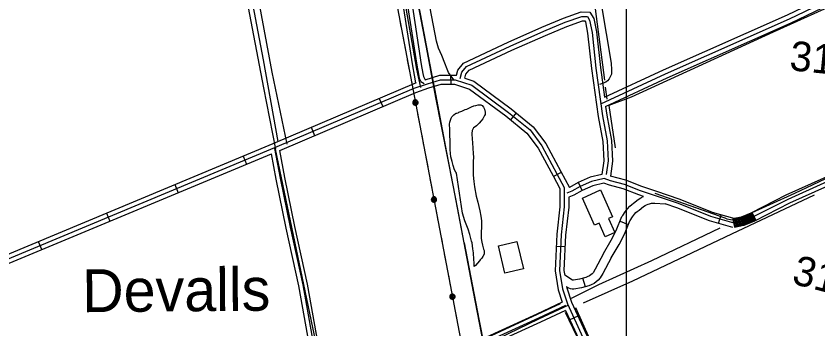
# Model space of a CAD drawing. Extents: x 3281947 to 3319794, y 715894 to 741249.
# Drawn here: x 3289265 to 3291976, y 736024 to 737081 of the extents above; entities that cross this region are included whole.
import ezdxf

# ---------------------------------------------------------------- set-up
doc = ezdxf.new("R2010")
doc.units = 0
for name, color, linetype in [('V-BLDG-OTLN', 7, 'Continuous'), ('V-DTCH-CNTR', 7, 'Continuous'), ('V-GRID-MAJR', 7, 'Continuous'), ('V-RAIL-TRAK', 7, 'Continuous'), ('V-ROAD-CNTR', 7, 'Continuous'), ('V-SITE-VEGE', 7, 'Continuous'), ('V-SURV-IDEN', 7, 'Continuous'), ('V-TOPO-GNAM-IDEN', 7, 'Continuous'), ('V-TOPO-SHOR', 7, 'Continuous'), ('V-UTIL-LINE', 7, 'Continuous')]:
    doc.layers.add(name, color=color, linetype=linetype)

msp = doc.modelspace()

# ---------------------------------------------------------------- linework, layer by layer
at = {"layer": 'V-BLDG-OTLN'}
for points in [[(3291281.8, 736402.7), (3291268.2, 736396.7), (3291289.1, 736349.7), (3291256.8, 736335.3), (3291236.1, 736381.7), (3291220.9, 736374.8), (3291180.2, 736466.2), (3291241.4, 736493.5)], [(3290958.2, 736319.6), (3290980.2, 736226.6), (3290917.7, 736211.8), (3290895.7, 736304.8)]]:
    msp.add_lwpolyline(points, close=True, dxfattribs=at)
at = {"layer": 'V-DTCH-CNTR'}
for points in [[(3290745.6, 736866.2), (3290727.6, 736890.9), (3290722.3, 736902.1), (3290714.4, 736922.2), (3290704.5, 736948), (3290693.2, 736973.1), (3290686.4, 736995.8), (3290608.7, 737401.9), (3290536.4, 737765.5), (3290428.6, 738333.3), (3290393, 738535.1), (3290545, 738549.1), (3290994.2, 738579.2), (3291010.3, 738578), (3291022.3, 738581), (3291034.6, 738586.7), (3291052.8, 738599.3), (3291065.5, 738604.9), (3291154.1, 738614), (3291554.3, 738636.3), (3291943.1, 738660), (3292376.8, 738680.9), (3292786.6, 738694), (3292937.7, 738730.9)], [(3291032.4, 738585.6), (3291072.4, 738319.9), (3291138.8, 737827.8), (3291242.7, 737123.1), (3291276.4, 736921.6), (3291278.1, 736899.7), (3291278.4, 736885.1), (3291270.6, 736869), (3291264.8, 736862.1), (3291259, 736857.5), (3291244.4, 736851.8), (3291238, 736849.9)], [(3290181.6, 736648), (3290131, 736891.1), (3290043.8, 737358.9), (3290013.9, 737491.6), (3289988.3, 737645.4), (3289930, 737941.6), (3289885.4, 738191.9), (3289823.9, 738505.8)], [(3289978.8, 737485.8), (3290020.7, 737264), (3290102.2, 736839), (3290142.3, 736631.8)], [(3290633.2, 736839.4), (3290619.8, 736901.3), (3290552.9, 737288.9)], [(3290314.7, 735730.3), (3290307.7, 735763), (3290298.4, 735883.4), (3290142.4, 736631.8)], [(3291133.2, 736103.4), (3291031.4, 736056.1), (3290894, 735990.4), (3290846.5, 735970.1)]]:
    msp.add_lwpolyline(points, dxfattribs=at)
at = {"layer": 'V-GRID-MAJR'}
msp.add_spline([(3291333.3, 721274), (3291331.5, 727333.8), (3291329.7, 733395.6), (3291328, 739457.3), (3291328, 739459.2)], degree=3, dxfattribs=at)
at = {"layer": 'V-RAIL-TRAK'}
for points in [[(3290780.3, 736314.3), (3290757.2, 736433.9), (3290722, 736620), (3290680.9, 736835.5), (3290673.1, 736874.7), (3290632.7, 737089.1), (3290589.9, 737311.7), (3290545.4, 737544.7), (3290504.4, 737757.4), (3290479.9, 737886.3), (3290444.8, 738070.3), (3290404.9, 738279.3), (3290360.8, 738509.8), (3290343.6, 738600.9), (3290298.1, 738836.8), (3290271.7, 738975.7), (3290237.6, 739154), (3290209.7, 739299.3), (3290186.4, 739422.1), (3290179.4, 739458.6)], [(3290780.3, 736314.3), (3290830.7, 736051.5), (3290846.4, 735970.5), (3290889.8, 735740.8), (3290942.3, 735469.4), (3291020.2, 735058.8), (3291065.3, 734823.3), (3291076.5, 734767.4), (3291091.3, 734689.9), (3291149.4, 734384.3), (3291181.5, 734219.5), (3291239.8, 733915.7), (3291314, 733529.1)]]:
    msp.add_lwpolyline(points, dxfattribs=at)
at = {"layer": 'V-ROAD-CNTR'}
for p, q in [((3290734.4, 736881.1), (3290734.5, 736851.1)), ((3290492.8, 736803.1), (3290504.6, 736775.5)), ((3290955.5, 736753.8), (3290936.6, 736730.5)), ((3290262.9, 736705.1), (3290274.6, 736677.5)), ((3290032.6, 736607.9), (3290044.2, 736580.2)), ((3291108.4, 736552.7), (3291081.9, 736538.7)), ((3289801.9, 736511.6), (3289813.5, 736483.9)), ((3291178.4, 736491.5), (3291166.4, 736519)), ((3289571.2, 736415.3), (3289582.8, 736387.6)), ((3291640, 736380.3), (3291648.2, 736409.2)), ((3291766.8, 736390.6), (3291753.3, 736417.3)), ((3291307, 736387.7), (3291334.8, 736376.4)), ((3289340.5, 736319), (3289352.1, 736291.3)), ((3291120.9, 736301.5), (3291090.9, 736302.8)), ((3291189.8, 736166), (3291181.6, 736194.8)), ((3291164.5, 736066.7), (3291137.2, 736054.2))]:
    msp.add_line(p, q, dxfattribs=at)
for points in [[(3290886.8, 735758.9), (3290812, 736149.3), (3290743.6, 736503.8), (3290684.6, 736806.4), (3290656.4, 736958.5), (3290548.8, 737517.9), (3290453.2, 738000.2), (3290363.1, 738472.4), (3290315, 738745.8), (3290226.2, 739200.2), (3290176.4, 739461.4)], [(3290268.9, 738539.2), (3290285.3, 738532.7), (3290304.8, 738512.6), (3290319.6, 738485), (3290337.2, 738443), (3290364.8, 738252.8), (3290377.4, 738195.5), (3290432.7, 737922.3), (3290500.7, 737628.6), (3290547.2, 737393.3), (3290603.8, 737119.1), (3290634.8, 736918), (3290640, 736887.3), (3290642.2, 736876.6), (3290648.1, 736865.6)], [(3290257.8, 738511.4), (3290268.2, 738507.2), (3290280.3, 738494.7), (3290292.5, 738472), (3290308.1, 738434.9), (3290335.3, 738247.5), (3290348, 738189.3), (3290403.4, 737915.9), (3290471.4, 737622.3), (3290517.8, 737387.3), (3290574.3, 737113.8), (3290605.2, 736913.2), (3290610.5, 736881.8), (3290615.9, 736855.5)], [(3290263.4, 738525.3), (3290276.8, 738519.9), (3290292.6, 738503.6), (3290306.1, 738478.5), (3290322.7, 738438.9), (3290350, 738250.2), (3290362.7, 738192.4), (3290418, 737919.1), (3290486, 737625.5), (3290532.5, 737390.3), (3290589, 737116.5), (3290620, 736915.6), (3290625.3, 736884.6), (3290628, 736871.4), (3290633.9, 736860.3), (3290644.5, 736853.7)], [(3291241.4, 736787.2), (3291241.7, 736784.6), (3291460.3, 736885.8), (3291879.5, 737072.1), (3292223, 737237.4), (3292795.7, 737492.3), (3292914.8, 737541.1), (3292968, 737567.7), (3293028.6, 737610.2), (3293062.5, 737666.1), (3293080.1, 737727.3), (3293105.3, 737794.5), (3293119.6, 737822.1), (3293150.7, 737838.2), (3293189.3, 737842.9), (3293244.7, 737860.5), (3293372, 737886.6), (3293435.9, 737899.1), (3293463.4, 737912.1), (3293491.3, 737922.1), (3293510.8, 737922.1)], [(3291258.1, 736775.6), (3291466.5, 736872.1), (3291885.8, 737058.5), (3292229.3, 737223.7), (3292801.6, 737478.5), (3292921.1, 737527.5), (3292975.7, 737554.8), (3293039.8, 737599.8), (3293076.4, 737660.1), (3293094.4, 737722.6), (3293119, 737788.4), (3293130.8, 737811), (3293155.2, 737823.7), (3293192.5, 737828.2), (3293248.5, 737845.9), (3293374.9, 737871.9), (3293440.6, 737884.7), (3293469.1, 737898.2), (3293493.9, 737907.1), (3293506.2, 737907.1)], [(3291253.9, 736806.8), (3291454.1, 736899.4), (3291873.2, 737085.7), (3292216.7, 737251), (3292427.8, 737344.9)], [(3290753.7, 736881.2), (3290758.9, 736898.8), (3290778.3, 736922.5), (3290929.1, 736992.8), (3291042.9, 737043.5), (3291116.2, 737074.1), (3291175.6, 737095), (3291205.2, 737094.3), (3291218.2, 737072.9), (3291227, 737027.9), (3291240.5, 736907.1), (3291253.9, 736806.8)], [(3290766.1, 736870.4), (3290772.4, 736891.6), (3290787.8, 736910.3), (3290935.3, 736979.2), (3291048.8, 737029.7), (3291121.5, 737060.1), (3291178, 737080), (3291196.7, 737079.5), (3291204, 737067.4), (3291212.2, 737025.6), (3291225.6, 736905.2), (3291247.2, 736744), (3291263.4, 736659), (3291266.8, 736591.3), (3291260.1, 736545.7)], [(3290782, 736871.4), (3290786, 736884.4), (3290797.2, 736898.2), (3290941.5, 736965.5), (3291054.8, 737016), (3291126.9, 737046.1), (3291180.4, 737064.9), (3291188.1, 737064.7), (3291189.8, 737061.9), (3291197.4, 737023.4), (3291210.7, 736903.4), (3291232.4, 736741.6), (3291248.5, 736657.2), (3291251.7, 736592.1), (3291244.9, 736545.4)], [(3292925.4, 736982.2), (3292913.3, 736977.5), (3292820.1, 736927.3), (3292579.1, 736805.6), (3292123.6, 736590.9), (3291867.3, 736475.3), (3291748.8, 736415), (3291716, 736401.8), (3291686.7, 736395.3)], [(3292930.8, 736968.2), (3292919.7, 736963.9), (3292827, 736914), (3292585.7, 736792.1), (3292129.9, 736577.3), (3291873.8, 736461.7), (3291755, 736401.4), (3291720.4, 736387.4), (3291689.9, 736380.7)], [(3292936.3, 736954.2), (3292926, 736950.2), (3292834, 736900.7), (3292592.3, 736778.6), (3292136.1, 736563.7), (3291880.2, 736448.2), (3291761.2, 736387.7), (3291724.9, 736373.1), (3291693.2, 736366)], [(3290648.1, 736865.6), (3290698.1, 736881), (3290753.7, 736881.2)], [(3286857.3, 734823), (3286878.9, 734837.3), (3287235, 735145.3), (3287700.1, 735562.8), (3287789.7, 735640.6), (3287842.8, 735673), (3288015.8, 735751.1), (3288317.9, 735887.9), (3289230.7, 736273.2), (3290134.7, 736650.5), (3290618.8, 736856.8)], [(3289236.5, 736259.3), (3290140.5, 736636.7), (3290610.8, 736837.1), (3290656, 736852.3), (3290700.4, 736866), (3290749.6, 736866.2), (3290805.5, 736848.1), (3290929.9, 736755.2), (3291002.9, 736696.1), (3291043, 736642.7), (3291093.7, 736548.4), (3291118.3, 736502.1), (3291118.3, 736435.9), (3291107.6, 736342.2), (3291102.3, 736220.8), (3291112.3, 736159.3), (3291128.8, 736108.6), (3291180.7, 735995.2), (3291318.5, 735695.6), (3291379, 735564.7), (3291428.4, 735472.4), (3291519, 735320.2), (3291679.9, 735056.4)], [(3290782, 736871.4), (3290812.5, 736861.6), (3290939.1, 736767.1), (3291013.7, 736706.6), (3291055.7, 736650.8), (3291106.9, 736555.5), (3291135.5, 736501.8)], [(3290156.8, 736627.3), (3290616.2, 736823), (3290660.6, 736838.1), (3290702.7, 736851), (3290747.3, 736851.2), (3290798.5, 736834.6), (3290920.7, 736743.4), (3290992, 736685.6), (3291030.3, 736634.6), (3291080.4, 736541.4), (3291103.3, 736498.4), (3291103.3, 736436.7), (3291092.7, 736343.4), (3291087.2, 736219.9), (3291097.7, 736155.8), (3291111.3, 736113.9)], [(3291258.1, 736775.6), (3291262, 736746.4), (3291278.3, 736660.8), (3291281.9, 736590.6), (3291274.5, 736540.2)], [(3288252, 735825.2), (3288330, 735860.4), (3289242.3, 736245.5), (3290128.5, 736615.4)], [(3290293.7, 735737.2), (3290283.4, 735827.6), (3290251.4, 735999.1), (3290221.4, 736169.3), (3290178.5, 736364.1), (3290144.5, 736530), (3290128.5, 736615.4)], [(3290314.4, 735733.1), (3290309.8, 735728.2), (3290298.3, 735829.8), (3290266.2, 736001.8), (3290236.2, 736172.2), (3290193.2, 736367.2), (3290159.2, 736532.9), (3290140.4, 736633.7)], [(3290322.4, 735750.5), (3290313.1, 735832), (3290281, 736004.4), (3290250.9, 736175.1), (3290207.8, 736370.3), (3290174, 736535.8), (3290156.8, 736627.3)], [(3291692.2, 736381.2), (3291614.1, 736403.3), (3291504.5, 736447.4), (3291423.6, 736475.1), (3291375.6, 736491), (3291322.1, 736511.9), (3291275, 736524.5), (3291252.9, 736531.9), (3291210.2, 736521.8), (3291172.4, 736505.2), (3291144.1, 736489.4), (3291126.6, 736482.4)], [(3291244.9, 736545.4), (3291205.4, 736536.1), (3291165.7, 736518.7), (3291135.5, 736501.8)], [(3291696.3, 736395.6), (3291619, 736417.5), (3291509.8, 736461.4), (3291428.4, 736489.3), (3291380.7, 736505.2), (3291326.8, 736526.2), (3291274.5, 736540.2)], [(3291386.7, 736471.6), (3291370.6, 736476.9), (3291317.4, 736497.6), (3291270.7, 736510.1), (3291252.2, 736516.3), (3291215, 736507.5), (3291179.1, 736491.8), (3291150.6, 736475.9), (3291133.3, 736468.9)], [(3291133.3, 736468.9), (3291133.3, 736435), (3291122.6, 736341.1), (3291117.3, 736221.7), (3291120.1, 736204.8)], [(3291250.9, 736278.6), (3291277.4, 736323.9), (3291294.3, 736356.4), (3291313.3, 736403.2), (3291316.3, 736407.6), (3291324.4, 736419.8), (3291332, 736430.1), (3291340.2, 736438.9), (3291346.5, 736444.2), (3291352.5, 736448.5), (3291367.8, 736461.4), (3291376.9, 736467.2), (3291384.6, 736470.9), (3291386.6, 736471.7)], [(3291276.8, 736263.5), (3291303.6, 736309.3), (3291321.6, 736343.8), (3291339.8, 736388.8), (3291341.1, 736390.6), (3291349.1, 736402.7), (3291355.2, 736411), (3291360.8, 736417), (3291364.8, 736420.4), (3291371, 736424.8), (3291385.7, 736437.2), (3291391.6, 736441), (3291396.5, 736443.3), (3291401.4, 736445.2), (3291406.5, 736446.8), (3291410.3, 736448), (3291412.9, 736448.4), (3291416.4, 736448.9), (3291420.3, 736449), (3291424.7, 736449.1), (3291459.8, 736446.7)], [(3291688.1, 736366.7), (3291609.3, 736389), (3291499.3, 736433.3), (3291459.5, 736447)], [(3291754.6, 736414.6), (3291750, 736412.3), (3291716.9, 736398.9), (3291687.3, 736392.4)], [(3291756, 736412), (3291751.3, 736409.6), (3291717.8, 736396.1), (3291688, 736389.4)], [(3291757.3, 736409.3), (3291752.5, 736406.8), (3291718.6, 736393.2), (3291688.6, 736386.5)], [(3291758.7, 736406.6), (3291753.8, 736404.1), (3291719.5, 736390.3), (3291689.3, 736383.6)], [(3291760, 736403.9), (3291755, 736401.4), (3291720.4, 736387.4), (3291689.9, 736380.7)], [(3291761.4, 736401.3), (3291756.2, 736398.6), (3291721.3, 736384.6), (3291690.6, 736377.7)], [(3291762.8, 736398.6), (3291757.5, 736395.9), (3291722.2, 736381.7), (3291691.2, 736374.8)], [(3291764.1, 736395.9), (3291758.7, 736393.2), (3291723.1, 736378.8), (3291691.9, 736371.9)], [(3291765.5, 736393.2), (3291760, 736390.4), (3291724, 736375.9), (3291692.5, 736368.9)], [(3291250.6, 736278.1), (3291222.9, 736226), (3291215.5, 736213.7), (3291212.7, 736210.4), (3291203.1, 736203.1), (3291196.3, 736199.5), (3291191.8, 736197.7), (3291170.1, 736191.5), (3291149.4, 736188.1), (3291148.5, 736188.1), (3291147.4, 736188.3), (3291146.3, 736188.7), (3291120.4, 736204.9)], [(3291277.1, 736264), (3291249, 736211.2), (3291239.8, 736196), (3291233.3, 736188.4), (3291219.2, 736177.7), (3291208.9, 736172.3), (3291201.7, 736169.3), (3291176.7, 736162.2), (3291151.1, 736157.9), (3291145.1, 736158.2), (3291139.9, 736159.2), (3291133.3, 736161.4), (3291126.4, 736165.7)], [(3291126.2, 736167), (3291126.9, 736162.9), (3291142.8, 736114.1), (3291194.3, 736001.5), (3291332.1, 735701.9), (3291392.4, 735571.3), (3291441.4, 735479.7), (3291531.8, 735328), (3291687.2, 735073.2)], [(3291122.6, 736102.7), (3291031.5, 736059.8), (3290861.7, 735982.5), (3290753, 735933.3), (3290384.5, 735762.9), (3290168.2, 735662.3), (3289600.4, 735395.5), (3288922.6, 735081.4), (3288887.5, 735065.8), (3288772.5, 735026.1), (3288585.9, 734954), (3288457.2, 734906.1), (3288438, 734961.8), (3288400.5, 735153.3), (3288340.3, 735404.1), (3288287.1, 735638.6), (3288251.6, 735774.8), (3288242.6, 735805), (3288235.3, 735828.3)], [(3291111.3, 736113.9), (3291025.2, 736073.4), (3290855.5, 735996.2), (3290746.7, 735947), (3290378.2, 735776.5), (3290322.4, 735750.5)], [(3291122.6, 736086.1), (3291037.8, 736046.2), (3290867.9, 735968.8), (3290759.2, 735919.7), (3290390.8, 735749.3), (3290174.5, 735648.7), (3289606.8, 735381.9), (3288928.8, 735067.8), (3288893.1, 735051.8), (3288777.7, 735012), (3288591.2, 734940), (3288448, 734886.7)], [(3291122.6, 736086.1), (3291167.1, 735989), (3291304.9, 735689.3), (3291365.6, 735558), (3291415.3, 735465), (3291506.1, 735312.5), (3291660, 735060.1)]]:
    msp.add_lwpolyline(points, dxfattribs=at)
at = {"layer": 'V-SITE-VEGE'}
msp.add_lwpolyline([(3290731.9, 736701.8), (3290730.5, 736710.9), (3290730.5, 736715.4), (3290732.1, 736722.9), (3290735.1, 736732.6), (3290735.9, 736735.6), (3290738.2, 736740.1), (3290745, 736747.6), (3290750.3, 736751.3), (3290753.3, 736752.8), (3290755.6, 736753.5), (3290759.3, 736754.3), (3290761.6, 736755.8), (3290768.4, 736758.7), (3290772.1, 736760.2), (3290776.7, 736761.7), (3290783.4, 736765.4), (3290788.7, 736766.8), (3290797.8, 736771.3), (3290805.3, 736774.3), (3290812.8, 736778), (3290819.6, 736779.4), (3290827.9, 736780.9), (3290836.1, 736780.8), (3290840.6, 736778.5), (3290845.1, 736773.2), (3290848.8, 736766.4), (3290851, 736755.9), (3290851, 736748.4), (3290848.7, 736744.7), (3290842.6, 736734.2), (3290838, 736727.4), (3290830.5, 736719.2), (3290821.4, 736710.3), (3290816.9, 736707.3), (3290811.6, 736703.6), (3290807, 736694.6), (3290806.2, 736684.1), (3290806.8, 736663.8), (3290808.3, 736655.5), (3290809.6, 736632.9), (3290811, 736619.4), (3290811.7, 736602.1), (3290810.9, 736591.6), (3290810.5, 736543.5), (3290812.7, 736522.5), (3290815.5, 736503.7), (3290820.6, 736472.8), (3290825.7, 736452.5), (3290833, 736422.4), (3290835.9, 736404.3), (3290838.1, 736388.5), (3290837.7, 736329.2), (3290839.9, 736316.4), (3290842, 736306.6), (3290845.7, 736293.8), (3290847.9, 736288.5), (3290847.9, 736281), (3290847.1, 736276.5), (3290843.3, 736268.3), (3290839.5, 736263), (3290836.5, 736260), (3290834.2, 736257.1), (3290831.9, 736253.3), (3290818.3, 736237.6), (3290813.8, 736234.6), (3290813.8, 736247.4), (3290812.4, 736258.7), (3290811.1, 736281.2), (3290809.6, 736294), (3290806.8, 736314.3), (3290804.6, 736320.4), (3290799.4, 736342.9), (3290793.6, 736360.3), (3290782.5, 736388.9), (3290774.4, 736414.5), (3290754.2, 736550.6), (3290752, 736553.7), (3290747.5, 736561.2), (3290742.4, 736576.3), (3290739.4, 736589.1), (3290735, 736605.6), (3290734.4, 736616.9), (3290732.2, 736630.4), (3290732.4, 736663.5), (3290731.7, 736674)], close=True, dxfattribs=at)
at = {"layer": 'V-TOPO-SHOR'}
for p, q in [((3291263.4, 736800.8), (3291257.2, 736840.8)), ((3291104.8, 736108.5), (3290857.1, 735993.8))]:
    msp.add_line(p, q, dxfattribs=at)
for points in [[(3291255.1, 736864.9), (3291183, 737417.2), (3291080.3, 738149.6), (3291018.5, 738565.7)], [(3293494.4, 737785.2), (3293201.7, 737660.2), (3292864.3, 737500.1), (3292411.4, 737292.6), (3291825, 737027), (3291344.5, 736807), (3291268.9, 736779.4), (3291289.9, 736635.4)], [(3289998.9, 737467.2), (3290100.2, 736932.9), (3290149.7, 736656.7)], [(3291424.4, 736482.1), (3291660.8, 736398.7), (3291668, 736396.3), (3291680.1, 736393.1), (3291689.5, 736392.7), (3291702.7, 736395.2), (3291714.5, 736400), (3291729.1, 736406.4), (3291897.8, 736483.1), (3292021.4, 736541.4)], [(3291963.2, 736475.6), (3291683.2, 736344.2), (3291348.9, 736185.6), (3291182.6, 736110.7)], [(3291143.3, 736127.5), (3291235.1, 736174), (3291414.3, 736254.8), (3291645.4, 736365.4)], [(3291156.1, 736096.2), (3291312.8, 735745.3), (3291406.8, 735541), (3291609.9, 735621.4), (3291803.4, 735696.6), (3292017.6, 735781.9), (3292275.3, 735884.8), (3292343.5, 735912.4), (3292671.7, 736040), (3292918.1, 736142.2)], [(3291121.7, 736080.2), (3291237.4, 735838.6), (3291370.2, 735542.5), (3291431.8, 735432.5), (3291572, 735199.5), (3291660.4, 735055.2)]]:
    msp.add_lwpolyline(points, dxfattribs=at)
at = {"layer": 'V-UTIL-LINE'}
for points in [[(3290106.1, 739458.5), (3290330.7, 738283.9), (3290559.1, 737084), (3290785.9, 735894.2), (3290899.5, 735297.4), (3291017.3, 734692.5), (3291128.9, 734105.7), (3291356.8, 732913.2), (3291474.1, 732317.9), (3291585.8, 731719.9), (3291701.1, 731121.7), (3291817.6, 730525.1), (3291929.6, 729931.5)], [(3290560.1, 737078.6), (3290566.4, 737045.2)], [(3290573.9, 737006), (3290580.3, 736972.6)], [(3290587.8, 736933.3), (3290594.2, 736899.9)], [(3290601.7, 736860.6), (3290608, 736827.2)], [(3290615.3, 736788.9), (3290617.3, 736790.9), (3290615, 736791.3), (3290613.2, 736789.3), (3290614, 736786.5), (3290617.4, 736787), (3290620.1, 736790.8), (3290617.7, 736794.3), (3290612.8, 736794.6), (3290610.1, 736791), (3290609.9, 736786.5), (3290613.6, 736783.4), (3290619.1, 736784.2), (3290624.2, 736790.5), (3290622.8, 736793.8), (3290620.4, 736796.3), (3290617.2, 736797.7), (3290613.6, 736797.7), (3290610.4, 736796.4), (3290607.9, 736793.9), (3290606.5, 736790.7), (3290606.5, 736787.2), (3290607.8, 736783.9), (3290610.3, 736781.4), (3290613.5, 736780), (3290617, 736780), (3290620.3, 736781.3), (3290622.8, 736783.8), (3290624.1, 736787), (3290624.2, 736790.5)], [(3290622.6, 736750.6), (3290629, 736717.2)], [(3290636.5, 736677.9), (3290642.9, 736644.5)], [(3290650.3, 736605.2), (3290656.7, 736571.8)], [(3290664.2, 736532.5), (3290670.6, 736499.1)], [(3290677.9, 736460.8), (3290679.9, 736462.8), (3290677.6, 736463.2), (3290675.7, 736461.2), (3290676.6, 736458.4), (3290679.9, 736458.9), (3290682.7, 736462.7), (3290680.2, 736466.2), (3290675.4, 736466.6), (3290672.6, 736462.9), (3290672.5, 736458.4), (3290676.2, 736455.4), (3290681.6, 736456.1), (3290686.7, 736462.5), (3290685.4, 736465.7), (3290682.9, 736468.2), (3290679.7, 736469.6), (3290676.2, 736469.6), (3290672.9, 736468.3), (3290670.4, 736465.8), (3290669.1, 736462.6), (3290669, 736459.1), (3290670.4, 736455.8), (3290672.8, 736453.3), (3290676, 736452), (3290679.6, 736451.9), (3290682.8, 736453.2), (3290685.3, 736455.7), (3290686.7, 736458.9), (3290686.7, 736462.5)], [(3290685.2, 736422.5), (3290691.5, 736389.1)], [(3290699, 736349.8), (3290705.4, 736316.4)], [(3290712.9, 736277.1), (3290719.3, 736243.7)], [(3290726.7, 736204.4), (3290733.1, 736171)], [(3290740.4, 736132.7), (3290742.4, 736134.7), (3290740.1, 736135.1), (3290738.3, 736133.1), (3290739.1, 736130.3), (3290742.5, 736130.8), (3290745.2, 736134.6), (3290742.8, 736138.1), (3290737.9, 736138.5), (3290735.1, 736134.8), (3290735, 736130.3), (3290738.7, 736127.3), (3290744.2, 736128), (3290749.3, 736134.4), (3290747.9, 736137.6), (3290745.5, 736140.1), (3290742.2, 736141.5), (3290738.7, 736141.5), (3290735.5, 736140.2), (3290733, 736137.7), (3290731.6, 736134.5), (3290731.6, 736131), (3290732.9, 736127.7), (3290735.4, 736125.2), (3290738.6, 736123.9), (3290742.1, 736123.8), (3290745.4, 736125.2), (3290747.9, 736127.6), (3290749.2, 736130.8), (3290749.3, 736134.4)], [(3290747.7, 736094.4), (3290754.1, 736061)]]:
    msp.add_lwpolyline(points, dxfattribs=at)

# ---------------------------------------------------------------- texts
at = {"layer": 'V-SURV-IDEN'}
for s, rotation, p in [('3178+20.0', 354.2315, (3291877.2, 736898.6)), ('3187+98.4', 345.6452, (3291883.8, 736177.9))]:
    msp.add_text(s, height=100, rotation=rotation, dxfattribs=at).set_placement(p)
at = {"layer": 'V-TOPO-GNAM-IDEN'}
msp.add_text('Devalls', height=145, rotation=0.4943, dxfattribs=at).set_placement((3289489.6, 736080.1))

doc.saveas('drawing.dxf')
